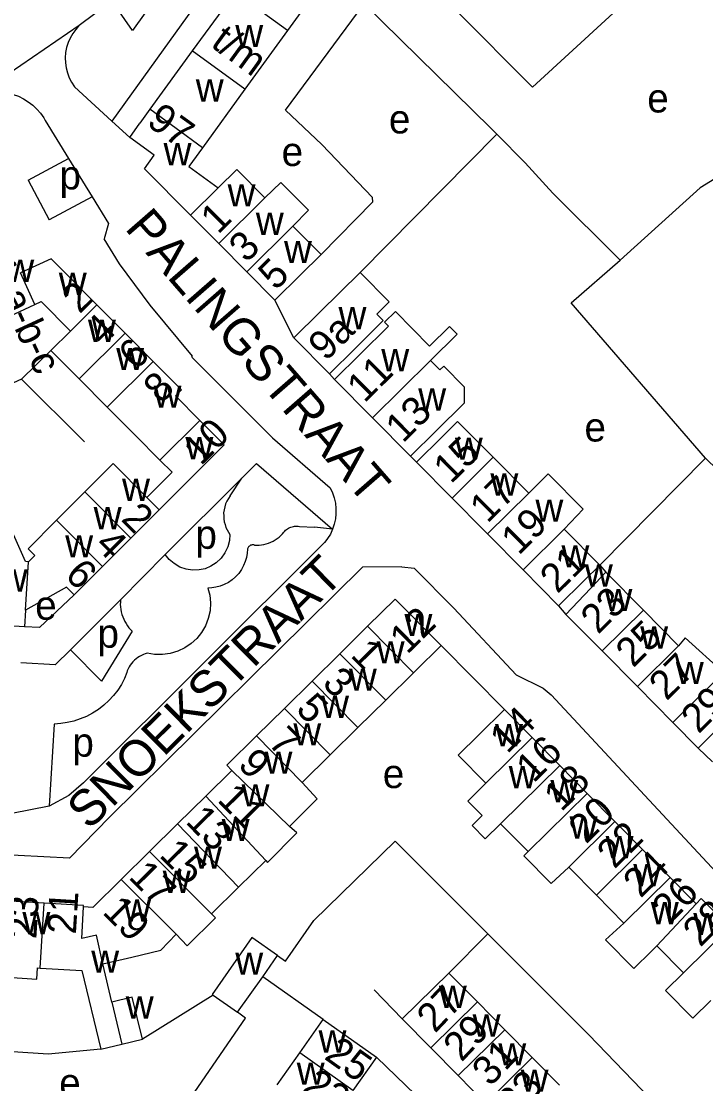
# Model space of a CAD drawing. Extents: x 159700 to 161346, y 381730 to 382922.
# Drawn here: x 160594.1 to 160688.9, y 382582.1 to 382729.2 of the extents above; entities that cross this region are included whole.
import ezdxf

# ---------------------------------------------------------------- set-up
doc = ezdxf.new("R2010")
doc.units = 0
for name, color, linetype in [('BLT_Basislijn', 7, 'Continuous'), ('BLT_Bebouwing', 7, 'Continuous'), ('BLT_Centroide', 7, 'Continuous'), ('BLT_Huisnummer', 7, 'Continuous'), ('BLT_Huisnummer_ tussenligend', 7, 'Continuous'), ('BLT_Huisnummer_reeks', 7, 'Continuous'), ('BLT_Onderdoorgang_en_onderverdeling', 7, 'Continuous'), ('BLT_Onderverdeling_panden', 7, 'Continuous'), ('BLT_Straatnaam', 7, 'Continuous'), ('BLT_Vlakafsluiter', 7, 'Continuous')]:
    doc.layers.add(name, color=color, linetype=linetype)

msp = doc.modelspace()

# ---------------------------------------------------------------- linework, layer by layer
at = {"layer": 'BLT_Basislijn'}
for p, q in [((160632.8, 382751.71), (160606.71, 382715.36)), ((160617.29, 382738.67), (160609.56, 382727.91)), ((160602.18, 382728.61), (160606.71, 382731.99)), ((160609.56, 382727.91), (160606.71, 382731.99)), ((160601.52, 382720.11), (160606.71, 382715.36)), ((160606.71, 382715.36), (160609.19, 382713.09)), ((160660.02, 382713.52), (160641.07, 382694.4)), ((160595.09, 382707.16), (160600.71, 382710.17)), ((160595.09, 382707.16), (160598.02, 382701.68)), ((160603.97, 382704.87), (160598.02, 382701.68)), ((160631.91, 382685.36), (160629.29, 382690.56)), ((160598.26, 382683.58), (160594.18, 382679.64)), ((160637.54, 382679.56), (160636.84, 382680.36)), ((160594.18, 382679.64), (160572.14, 382669.39)), ((160594.18, 382679.64), (160602.92, 382670.96)), ((160628.93, 382671.5), (160636.95, 382664.56)), ((160648.88, 382668.14), (160648.05, 382668.95)), ((160674.27, 382653.9), (160688.9, 382668.67)), ((160700, 382657.9), (160688.9, 382668.67)), ((160624.71, 382665.92), (160626.75, 382667.95)), ((160626.75, 382667.95), (160637.27, 382658.85)), ((160614.1, 382655.34), (160624.71, 382665.92)), ((160623.06, 382663.46), (160624.71, 382665.92)), ((160632.68, 382659.24), (160634.78, 382659.12)), ((160637.27, 382658.85), (160634.78, 382659.12)), ((160636.16, 382657), (160602.77, 382623.76)), ((160636.49, 382657.43), (160636.16, 382657)), ((160614.1, 382655.34), (160607.9, 382649.1)), ((160607.9, 382649.1), (160600.95, 382642.16)), ((160609.51, 382644.72), (160605.25, 382637.83)), ((160598.86, 382640.07), (160600.95, 382642.16)), ((160600.95, 382642.16), (160605.25, 382637.83)), ((160652.31, 382642.74), (160661.07, 382633.9)), ((160598.86, 382640.07), (160594.11, 382640.37)), ((160598.72, 382631.89), (160598.03, 382620.53)), ((160689.9, 382626.67), (160687.91, 382628.56)), ((160602.77, 382623.76), (160600.72, 382622.01)), ((160600.72, 382622.01), (160598.03, 382620.53)), ((160598.03, 382620.53), (160592.85, 382619.51)), ((160653.35, 382597.42), (160658.77, 382602.84)), ((160658.77, 382602.84), (160672.75, 382588.87)), ((160635.96, 382590.98), (160627.6, 382596.91)), ((160646.92, 382591.08), (160643.02, 382595.08)), ((160625.22, 382591.19), (160624.12, 382591.99)), ((160615.96, 382577.74), (160625.22, 382591.19)), ((160682.67, 382578.61), (160672.75, 382588.87)), ((160643.35, 382585.79), (160650.07, 382579.26))]:
    msp.add_line(p, q, dxfattribs=at)
for points in [[(160635.68, 382696.9), (160642.83, 382704.15), (160642.78, 382704.76), (160635.77, 382712.11), (160630.74, 382716.84), (160641.65, 382731.58)], [(160660.02, 382713.52), (160659.18, 382714.37), (160641.65, 382731.58)], [(160602.18, 382728.61), (160601.73, 382728.04), (160601.3, 382727.47), (160600.94, 382726.85), (160600.65, 382726.21), (160600.43, 382725.53), (160600.3, 382724.83), (160600.24, 382724.12), (160600.26, 382723.41), (160600.36, 382722.7), (160600.54, 382722.01), (160600.79, 382721.35), (160601.12, 382720.72), (160601.52, 382720.11)], [(160587.66, 382718.71), (160588.39, 382718.99), (160589.14, 382719.2), (160589.92, 382719.33), (160590.7, 382719.38), (160591.48, 382719.35), (160592.25, 382719.24), (160593.01, 382719.05), (160593.75, 382718.78), (160594.45, 382718.44), (160595.12, 382718.03), (160595.74, 382717.55), (160596.31, 382717.02), (160596.82, 382716.43), (160597.27, 382715.79), (160597.47, 382715.45)], [(160597.47, 382715.45), (160600.71, 382710.17)], [(160677.09, 382696.09), (160667.76, 382705.35), (160663.92, 382709.58), (160660.02, 382713.52)], [(160600.71, 382710.17), (160603.97, 382704.87)], [(160692.82, 382708.99), (160688.16, 382706.12), (160677.09, 382696.09)], [(160603.97, 382704.87), (160606.24, 382701.18), (160605.63, 382699.03)], [(160628.93, 382671.5), (160617.78, 382682.66), (160617.87, 382682.82), (160612.01, 382689.89), (160607.76, 382695.61), (160605.63, 382699.03)], [(160688.9, 382668.67), (160670.3, 382690.2), (160677.09, 382696.09)], [(160636.95, 382664.56), (160637.26, 382663.89), (160637.5, 382663.19), (160637.66, 382662.47), (160637.74, 382661.74), (160637.74, 382661), (160637.66, 382660.27), (160637.5, 382659.55), (160637.27, 382658.85)], [(160623.06, 382663.46), (160622.85, 382663.1), (160622.64, 382662.73), (160622.45, 382662.36), (160622.35, 382661.94), (160622.24, 382661.53), (160622.18, 382661.11), (160622.19, 382660.69), (160622.2, 382660.27), (160622.27, 382659.87), (160622.38, 382659.49), (160622.49, 382659.1), (160622.66, 382658.77), (160622.85, 382658.45), (160623.03, 382658.14)], [(160623.03, 382658.14), (160622.97, 382657.28), (160622.75, 382656.42), (160622.36, 382655.58), (160621.82, 382654.83), (160621.15, 382654.2), (160620.4, 382653.72), (160619.61, 382653.39), (160618.77, 382653.21), (160617.88, 382653.18), (160616.97, 382653.32), (160616.1, 382653.62), (160615.31, 382654.09), (160614.63, 382654.67), (160614.1, 382655.34)], [(160626.46, 382656.65), (160626.78, 382656.64), (160627.11, 382656.66), (160627.43, 382656.69), (160627.76, 382656.75), (160628.09, 382656.83), (160628.41, 382656.93), (160628.72, 382657.06), (160629.02, 382657.21), (160629.31, 382657.38), (160629.59, 382657.56), (160629.85, 382657.77), (160630.1, 382657.99), (160630.32, 382658.22), (160630.53, 382658.46)], [(160630.53, 382658.46), (160630.64, 382658.59), (160630.76, 382658.71), (160630.89, 382658.82), (160631.03, 382658.92), (160631.18, 382659.01), (160631.34, 382659.08), (160631.5, 382659.15), (160631.67, 382659.2), (160631.84, 382659.24), (160632.01, 382659.27), (160632.18, 382659.28), (160632.35, 382659.28), (160632.52, 382659.27), (160632.68, 382659.24)], [(160637.27, 382658.85), (160636.96, 382658.18), (160636.58, 382657.55), (160636.49, 382657.43)], [(160626.46, 382656.65), (160626.38, 382656.67), (160626.29, 382656.69), (160626.2, 382656.69), (160626.11, 382656.68), (160626.02, 382656.66), (160625.92, 382656.63), (160625.84, 382656.59), (160625.75, 382656.53), (160625.68, 382656.47), (160625.62, 382656.4), (160625.56, 382656.32), (160625.52, 382656.24), (160625.49, 382656.16), (160625.47, 382656.08)], [(160625.47, 382656.08), (160625.43, 382655.52), (160625.33, 382654.95), (160625.17, 382654.37), (160624.94, 382653.81), (160624.64, 382653.26), (160624.27, 382652.74), (160623.84, 382652.26), (160623.35, 382651.84), (160622.83, 382651.48), (160622.27, 382651.19), (160621.7, 382650.97), (160621.12, 382650.82), (160620.54, 382650.74), (160619.99, 382650.71)], [(160646.87, 382653.63), (160641.41, 382653.58), (160606.37, 382618.99), (160600.81, 382613.3), (160572.37, 382614.78)], [(160646.87, 382653.63), (160648.58, 382653.45), (160654.06, 382647.94), (160662.68, 382638.7), (160666.44, 382636.83), (160667.56, 382635.94), (160691.01, 382610.72), (160700, 382601.48)], [(160619.99, 382650.71), (160620.28, 382649.72), (160620.37, 382648.65), (160620.3, 382647.56), (160620.05, 382646.49), (160619.65, 382645.48), (160619.11, 382644.55), (160618.46, 382643.74), (160617.7, 382643.03), (160616.81, 382642.43), (160615.83, 382641.96), (160614.78, 382641.64), (160613.69, 382641.5), (160612.62, 382641.51), (160611.6, 382641.68)], [(160601.49, 382649.76), (160596.68, 382645.26), (160594.62, 382645.34)], [(160607.9, 382649.1), (160607.88, 382648.77), (160607.87, 382648.43), (160607.9, 382648.09), (160607.94, 382647.74), (160608.01, 382647.4), (160608.09, 382647.06), (160608.2, 382646.73), (160608.34, 382646.41), (160608.49, 382646.09), (160608.66, 382645.79), (160608.85, 382645.5), (160609.05, 382645.22), (160609.27, 382644.96), (160609.51, 382644.72)], [(160611.6, 382641.68), (160611.33, 382641.6), (160611.06, 382641.51), (160610.79, 382641.39), (160610.53, 382641.25), (160610.28, 382641.09), (160610.05, 382640.91), (160609.82, 382640.71), (160609.61, 382640.5), (160609.42, 382640.27), (160609.25, 382640.04), (160609.09, 382639.79), (160608.96, 382639.53), (160608.84, 382639.27), (160608.75, 382639)], [(160608.75, 382639), (160608.45, 382638.17), (160608.02, 382637.37), (160607.51, 382636.59), (160606.94, 382635.85), (160606.3, 382635.15), (160605.59, 382634.5), (160604.83, 382633.92), (160604.02, 382633.4), (160603.18, 382632.95), (160602.3, 382632.59), (160601.41, 382632.3), (160600.51, 382632.09), (160599.61, 382631.95), (160598.72, 382631.89)], [(160629.66, 382599.83), (160630.74, 382599.07), (160634.67, 382604.67), (160645.95, 382615.66), (160658.77, 382602.84)], [(160620.73, 382594.33), (160610.92, 382588.25)], [(160605.18, 382586.86), (160597.86, 382586.2), (160592.98, 382586.5), (160568.15, 382587.92)]]:
    msp.add_lwpolyline(points, dxfattribs=at)
at = {"layer": 'BLT_Bebouwing'}
for p, q in [((160636.99, 382736.15), (160631.01, 382727.89)), ((160623.72, 382733.18), (160617.84, 382725.08)), ((160631.01, 382727.89), (160625.11, 382719.75)), ((160617.84, 382725.08), (160611.96, 382716.99)), ((160625.11, 382719.75), (160619.24, 382711.65)), ((160611.96, 382716.99), (160610.56, 382715.06)), ((160609.19, 382713.09), (160610.56, 382715.06)), ((160619.24, 382711.65), (160617.88, 382709.77)), ((160611.2, 382708.75), (160617.6, 382702.32)), ((160617.6, 382702.32), (160621.5, 382698.39)), ((160631.78, 382700.82), (160635.68, 382696.9)), ((160621.5, 382698.39), (160625.4, 382694.48)), ((160604.64, 382689.92), (160600.57, 382694)), ((160625.4, 382694.48), (160629.29, 382690.56)), ((160596.05, 382689.97), (160596.9, 382690.37)), ((160596.9, 382690.37), (160600.95, 382686.27)), ((160591.89, 382688.04), (160596.05, 382689.97)), ((160608.54, 382686), (160604.64, 382689.92)), ((160600.95, 382686.27), (160598.26, 382683.58)), ((160612.44, 382682.08), (160608.54, 382686)), ((160631.91, 382685.36), (160636.84, 382680.36)), ((160602.16, 382679.66), (160606.06, 382675.74)), ((160642.79, 382674.26), (160637.54, 382679.56)), ((160618.89, 382673.9), (160615.51, 382677.3)), ((160606.06, 382675.74), (160609.97, 382671.81)), ((160648.05, 382668.95), (160642.79, 382674.26)), ((160609.97, 382671.81), (160613.36, 382668.41)), ((160664.43, 382663.84), (160659.5, 382668.81)), ((160653.81, 382663.17), (160648.88, 382668.14)), ((160602.94, 382664.01), (160599.02, 382660.09)), ((160658.23, 382658.7), (160653.81, 382663.17)), ((160613.26, 382661.54), (160609.34, 382657.61)), ((160658.73, 382658.2), (160658.23, 382658.7)), ((160663.65, 382653.23), (160658.73, 382658.2)), ((160609.34, 382657.61), (160605.41, 382653.69)), ((160605.41, 382653.69), (160601.49, 382649.76)), ((160674.27, 382653.9), (160675.12, 382652.89)), ((160668.57, 382648.25), (160663.65, 382653.23)), ((160594.76, 382647.64), (160594.62, 382645.34)), ((160668.57, 382648.25), (160669.58, 382647.07)), ((160685.18, 382642.73), (160680.31, 382647.65)), ((160669.58, 382647.07), (160674.59, 382642.02)), ((160594.62, 382645.34), (160589.14, 382645.68)), ((160642.12, 382645.41), (160638.28, 382641.62)), ((160674.59, 382642.02), (160679.49, 382637.06)), ((160638.28, 382641.62), (160634.43, 382637.83)), ((160644.62, 382635.17), (160648.47, 382638.96)), ((160634.43, 382637.83), (160630.59, 382634.04)), ((160679.49, 382637.06), (160684.4, 382632.1)), ((160640.77, 382631.39), (160644.62, 382635.17)), ((160630.59, 382634.04), (160626.74, 382630.24)), ((160664.89, 382630.03), (160661.07, 382633.9)), ((160684.4, 382632.1), (160687.91, 382628.56)), ((160636.92, 382627.6), (160640.77, 382631.39)), ((160668.72, 382626.16), (160664.89, 382630.03)), ((160633.07, 382623.81), (160636.92, 382627.6)), ((160672.54, 382622.28), (160668.72, 382626.16)), ((160623.31, 382625.47), (160619.69, 382621.9)), ((160619.69, 382621.9), (160615.8, 382618.06)), ((160676.37, 382618.41), (160672.54, 382622.28)), ((160680.2, 382614.53), (160676.37, 382618.41)), ((160615.8, 382618.06), (160611.9, 382614.22)), ((160664.34, 382614.23), (160660.54, 382618.08)), ((160611.9, 382614.22), (160608.01, 382610.38)), ((160684.02, 382610.66), (160680.2, 382614.53)), ((160673.8, 382608.21), (160669.97, 382612.09)), ((160687.63, 382607.01), (160684.02, 382610.66)), ((160677.62, 382604.34), (160673.8, 382608.21)), ((160597.32, 382607.09), (160591.87, 382607.43)), ((160602.77, 382606.75), (160597.32, 382607.09)), ((160602.76, 382606.59), (160602.77, 382606.75)), ((160687.63, 382607.01), (160688.33, 382607.75)), ((160692.27, 382603.76), (160688.33, 382607.75)), ((160685.85, 382597.44), (160682.17, 382601.17)), ((160627.6, 382596.91), (160629.66, 382599.83)), ((160624.12, 382591.99), (160627.6, 382596.91)), ((160646.92, 382591.08), (160653.35, 382597.42)), ((160653.35, 382597.42), (160657.32, 382593.41)), ((160620.58, 382594.44), (160620.73, 382594.33)), ((160620.73, 382594.33), (160624.12, 382591.99)), ((160657.32, 382593.41), (160661.1, 382589.57)), ((160689.65, 382593.6), (160687.18, 382591.16)), ((160632.71, 382586.36), (160635.96, 382590.98)), ((160650.87, 382587.07), (160646.92, 382591.08)), ((160661.1, 382589.57), (160664.9, 382585.74)), ((160629.6, 382581.92), (160632.71, 382586.36)), ((160654.67, 382583.22), (160650.87, 382587.07)), ((160664.9, 382585.74), (160668.69, 382581.9)), ((160658.46, 382579.36), (160654.67, 382583.22))]:
    msp.add_line(p, q, dxfattribs=at)
for points in [[(160654.37, 382730.68), (160664.96, 382720.03), (160686.18, 382739.55)], [(160612.56, 382710.61), (160609.19, 382713.09)], [(160611.2, 382708.75), (160612.56, 382710.61)], [(160617.88, 382709.77), (160617.37, 382709.06), (160621.42, 382706.11)], [(160621.42, 382706.11), (160623.99, 382708.65), (160627.88, 382704.74)], [(160627.88, 382704.74), (160630.1, 382706.86), (160633.92, 382703.02), (160631.78, 382700.82)], [(160600.57, 382694), (160598.28, 382696.3), (160594.03, 382694.34)], [(160629.29, 382690.56), (160632.84, 382694.09), (160635.68, 382696.9)], [(160631.91, 382685.36), (160635.51, 382688.89), (160641.07, 382694.4)], [(160636.84, 382680.36), (160640.39, 382683.88), (160644.28, 382687.73), (160643.39, 382688.63), (160645.1, 382690.32), (160641.07, 382694.4)], [(160637.54, 382679.56), (160641.09, 382683.08), (160645.02, 382686.98), (160644.48, 382687.53), (160645.96, 382689), (160650.7, 382684.21), (160653.45, 382686.93), (160654.51, 382685.86), (160650.83, 382682.22)], [(160598.26, 382683.58), (160602.16, 382679.66)], [(160615.51, 382677.3), (160616.35, 382678.15), (160612.44, 382682.08)], [(160650.83, 382682.22), (160652.13, 382680.9), (160652.67, 382681.43), (160655.51, 382678.56), (160655.47, 382676.3), (160651.6, 382672.47), (160648.05, 382668.95)], [(160618.89, 382673.9), (160622.25, 382670.52), (160613.26, 382661.54)], [(160648.88, 382668.14), (160652.44, 382671.66), (160654.58, 382673.78), (160659.5, 382668.81)], [(160613.36, 382668.41), (160615.03, 382666.73), (160611.54, 382663.24)], [(160611.54, 382663.24), (160606.86, 382667.93), (160602.94, 382664.01)], [(160669.35, 382658.87), (160671.97, 382661.62), (160667.13, 382666.51), (160664.43, 382663.84)], [(160599.02, 382660.09), (160595.09, 382656.16), (160596.03, 382655.21), (160595.15, 382654.33)], [(160595.15, 382654.33), (160594.73, 382654.38), (160592.87, 382658.52), (160589.73, 382656.87), (160589.7, 382654.67)], [(160669.35, 382658.87), (160674.27, 382653.9)], [(160675.12, 382652.89), (160680.31, 382647.65)], [(160601.49, 382649.76), (160600.4, 382650.85), (160594.76, 382647.64)], [(160652.31, 382642.74), (160645.93, 382649.17), (160642.12, 382645.41)], [(160690.12, 382637.75), (160691.39, 382639), (160686.1, 382643.81), (160685.18, 382642.73)], [(160648.47, 382638.96), (160648.75, 382639.24), (160652.31, 382642.74)], [(160658.49, 382623.71), (160654.66, 382627.59), (160657.51, 382630.39), (160661.07, 382633.9)], [(160687.91, 382628.56), (160691.46, 382632.08), (160693.62, 382634.21)], [(160626.74, 382630.24), (160622.62, 382626.19), (160623.31, 382625.47)], [(160631.31, 382617.72), (160635.11, 382621.52), (160633.07, 382623.81)], [(160660.54, 382618.08), (160658.41, 382615.98), (160656.58, 382617.83), (160657.99, 382619.22), (160656.02, 382621.21), (160658.49, 382623.71)], [(160628.01, 382613), (160628.26, 382612.73), (160632.32, 382616.83), (160631.31, 382617.72)], [(160669.97, 382612.09), (160667.54, 382609.79), (160663.74, 382613.64), (160664.34, 382614.23)], [(160624.25, 382609.3), (160628.01, 382613)], [(160608.01, 382610.38), (160604.06, 382606.48), (160602.76, 382606.59)], [(160620.5, 382605.59), (160624.25, 382609.3)], [(160615.62, 382602.79), (160617.15, 382601.17), (160621.05, 382605.07), (160620.5, 382605.59)], [(160682.17, 382601.17), (160681.45, 382600.46), (160678.98, 382598.03), (160675.06, 382602.01), (160677.62, 382604.34)], [(160605.47, 382598.71), (160609.47, 382599.63), (160613.46, 382600.56), (160615.62, 382602.79)], [(160629.66, 382599.83), (160626.1, 382602.34), (160620.58, 382594.44)], [(160591.32, 382598.45), (160591.64, 382598.43), (160591.55, 382596.88), (160596.29, 382596.58), (160596.38, 382598.14), (160596.77, 382598.11)], [(160596.77, 382598.11), (160602.54, 382597.76), (160605.18, 382586.86)], [(160606.7, 382593.4), (160605.47, 382598.71)], [(160687.18, 382591.16), (160683.38, 382595), (160685.85, 382597.44)], [(160610.92, 382588.25), (160609.51, 382594.08), (160606.7, 382593.4)], [(160635.96, 382590.98), (160643.35, 382585.79), (160640.09, 382581.15)], [(160605.18, 382586.86), (160608.06, 382587.56)], [(160608.06, 382587.56), (160610.92, 382588.25)]]:
    msp.add_lwpolyline(points, dxfattribs=at)
at = {"layer": 'BLT_Onderdoorgang_en_onderverdeling'}
for points in [[(160674.27, 382653.9), (160672.12, 382651.77), (160668.57, 382648.25)], [(160669.58, 382647.07), (160673, 382650.67), (160675.12, 382652.89)]]:
    msp.add_lwpolyline(points, dxfattribs=at)
at = {"layer": 'BLT_Onderverdeling_panden'}
for p, q in [((160631.01, 382727.89), (160623.72, 382733.18)), ((160625.11, 382719.75), (160617.84, 382725.08)), ((160619.24, 382711.65), (160611.96, 382716.99)), ((160617.6, 382702.32), (160621.42, 382706.11)), ((160621.5, 382698.39), (160627.88, 382704.74)), ((160625.4, 382694.48), (160631.78, 382700.82)), ((160596.05, 382689.97), (160594.03, 382694.34)), ((160600.95, 382686.27), (160604.64, 382689.92)), ((160602.16, 382679.66), (160608.54, 382686)), ((160606.06, 382675.74), (160612.44, 382682.08)), ((160642.79, 382674.26), (160650.83, 382682.22)), ((160618.89, 382673.9), (160613.36, 382668.41)), ((160653.81, 382663.17), (160659.5, 382668.81)), ((160609.34, 382657.61), (160602.94, 382664.01)), ((160658.73, 382658.2), (160664.43, 382663.84)), ((160611.54, 382663.24), (160613.26, 382661.54)), ((160605.41, 382653.69), (160599.02, 382660.09)), ((160663.65, 382653.23), (160669.35, 382658.87)), ((160594.76, 382647.64), (160595.15, 382654.33)), ((160674.59, 382642.02), (160680.31, 382647.65)), ((160648.47, 382638.96), (160642.12, 382645.41)), ((160679.49, 382637.06), (160685.18, 382642.73)), ((160644.62, 382635.17), (160638.28, 382641.62)), ((160640.77, 382631.39), (160634.43, 382637.83)), ((160684.4, 382632.1), (160690.12, 382637.75)), ((160636.92, 382627.6), (160630.59, 382634.04)), ((160633.07, 382623.81), (160626.74, 382630.24)), ((160658.49, 382623.71), (160664.89, 382630.03)), ((160660.54, 382618.08), (160668.72, 382626.16)), ((160631.31, 382617.72), (160623.31, 382625.47)), ((160628.01, 382613), (160619.69, 382621.9)), ((160664.34, 382614.23), (160672.54, 382622.28)), ((160669.97, 382612.09), (160676.37, 382618.41)), ((160624.25, 382609.3), (160615.8, 382618.06)), ((160620.5, 382605.59), (160611.9, 382614.22)), ((160673.8, 382608.21), (160680.2, 382614.53)), ((160615.62, 382602.79), (160608.01, 382610.38)), ((160677.62, 382604.34), (160684.02, 382610.66)), ((160596.77, 382598.11), (160597.32, 382607.09)), ((160682.17, 382601.17), (160687.63, 382607.01)), ((160685.85, 382597.44), (160692.27, 382603.76)), ((160606.7, 382593.4), (160608.06, 382587.56)), ((160650.87, 382587.07), (160657.32, 382593.41)), ((160661.1, 382589.57), (160654.67, 382583.22)), ((160640.09, 382581.15), (160632.71, 382586.36)), ((160658.46, 382579.36), (160664.9, 382585.74))]:
    msp.add_line(p, q, dxfattribs=at)
msp.add_lwpolyline([(160605.47, 382598.71), (160604.55, 382602.68), (160602.55, 382602.22), (160602.76, 382606.59)], dxfattribs=at)
at = {"layer": 'BLT_Vlakafsluiter'}
msp.add_line((160587.66, 382718.71), (160602.18, 382728.61), dxfattribs=at)

# ---------------------------------------------------------------- texts
at = {"layer": 'BLT_Centroide'}
for s, p in [('w', (160623.79, 382725.59)), ('w', (160618.32, 382718.06)), ('e', (160680.85, 382716.54)), ('e', (160645.07, 382713.64)), ('w', (160613.86, 382709.23)), ('e', (160630.21, 382709.13)), ('p', (160599.45, 382705.89)), ('w', (160622.73, 382703.53)), ('w', (160626.64, 382699.59)), ('w', (160630.54, 382695.69)), ('w', (160592.08, 382693.09)), ('w', (160599.35, 382691.28)), ('w', (160638.09, 382686.53)), ('w', (160603.39, 382684.78)), ('w', (160607.3, 382680.88)), ('w', (160644.01, 382680.72)), ('w', (160612.47, 382675.66)), ('w', (160649.13, 382675.28)), ('e', (160672.15, 382670.99)), ('w', (160616.89, 382668.53)), ('w', (160654.2, 382668.47)), ('w', (160608.11, 382662.77)), ('w', (160659.12, 382663.5)), ('w', (160665.36, 382659.88)), ('w', (160604.18, 382658.84)), ('w', (160600.24, 382654.94)), ('p', (160618.27, 382656.14)), ('w', (160668.96, 382653.56)), ('w', (160672.21, 382650.91)), ('w', (160591.17, 382650.23)), ('w', (160674.92, 382647.52)), ('e', (160596.08, 382646.32)), ('w', (160647.22, 382644.05)), ('p', (160604.71, 382642.45)), ('w', (160679.87, 382642.34)), ('w', (160643.38, 382640.28)), ('w', (160684.81, 382637.41)), ('w', (160639.53, 382636.5)), ('w', (160635.67, 382632.72)), ('w', (160631.83, 382628.92)), ('w', (160659.77, 382628.81)), ('p', (160601.23, 382627.37)), ('w', (160627.84, 382625)), ('e', (160644.22, 382623.02)), ('w', (160661.66, 382623)), ('w', (160667.43, 382621.06)), ('w', (160624.66, 382620.47)), ('w', (160621.91, 382615.69)), ('w', (160670.09, 382616.03)), ('w', (160675.08, 382613.31)), ('w', (160618.08, 382611.86)), ('w', (160678.91, 382609.44)), ('w', (160613.75, 382608.5)), ('w', (160608.26, 382604.53)), ('w', (160681.34, 382604.17)), ('w', (160594.31, 382602.78)), ('w', (160687.22, 382602.67)), ('w', (160603.84, 382597.45)), ('w', (160623.79, 382597.17)), ('w', (160651.99, 382592.59)), ('w', (160608.62, 382591.1)), ('w', (160656.66, 382588.61)), ('w', (160635.32, 382586.41)), ('w', (160660.22, 382584.63)), ('w', (160632.3, 382581.95)), ('e', (160599.41, 382580.22)), ('w', (160663.31, 382580.99))]:
    msp.add_text(s, height=4, dxfattribs=at).set_placement(p)
at = {"layer": 'BLT_Huisnummer'}
for s, rotation, p in [('1', 44.8469, (160621.42, 382699.58)), ('5', 44.8469, (160629.4, 382691.79)), ('2', 44.8648, (160602.22, 382688.57)), ('9a', 44.7083, (160636.33, 382681.99)), ('6', 44.7038, (160610.05, 382680.74)), ('11', 44.7069, (160641.68, 382676.23)), ('10', 44.6738, (160619.01, 382667.53)), ('15', 44.7083, (160653.66, 382665.02)), ('2', 314.9955, (160607.84, 382660.13)), ('19', 44.7171, (160663.04, 382655.15)), ('6', 314.9062, (160600.04, 382652.34)), ('23', 44.7083, (160674.05, 382644.21)), ('12', 44.53, (160647.59, 382641.42)), ('1', 314.5294, (160639.63, 382641.3)), ('5', 314.5287, (160632.03, 382633.78)), ('29', 44.7124, (160687.95, 382630.43)), ('14', 44.6397, (160661.46, 382627.65)), ('9', 314.6041, (160624, 382626.11)), ('18', 44.6396, (160668.94, 382619.62)), ('13', 314.6086, (160616.76, 382618.27)), ('22', 44.6395, (160676.3, 382611.72)), ('17', 314.6041, (160608.88, 382610.61)), ('26', 44.6398, (160683.95, 382604.12)), ('21', 86.4674, (160601.71, 382602.71)), ('27', 46.6261, (160651.45, 382588.98)), ('25', 324.6261, (160635.96, 382585.62)), ('31', 46.6261, (160659.12, 382581.58))]:
    msp.add_text(s, height=4, rotation=rotation, dxfattribs=at).set_placement(p)
at = {"layer": 'BLT_Huisnummer_ tussenligend'}
for s, rotation, p in [('3', 44.8469, (160625.34, 382695.62)), ('4', 44.8648, (160605.44, 382684.11)), ('8', 44.7038, (160613.49, 382676.1)), ('13', 44.7069, (160647.01, 382670.66)), ('17', 44.7083, (160658.7, 382659.56)), ('4', 314.9955, (160604.2, 382656.51)), ('21', 44.7171, (160668.41, 382649.82)), ('25', 44.7083, (160678.89, 382639.57)), ('27', 44.7124, (160683.51, 382635)), ('3', 314.5294, (160635.68, 382637.38)), ('7', 314.5287, (160628.18, 382629.14)), ('16', 44.6397, (160665.09, 382623.61)), ('11', 314.6041, (160621.17, 382621.28)), ('20', 44.6396, (160672.37, 382615.17)), ('15', 314.6086, (160613.13, 382613.62)), ('24', 44.6395, (160679.92, 382607.67)), ('23', 86.4674, (160596.23, 382602.06)), ('19', 314.6041, (160605.25, 382605.75)), ('28', 44.6398, (160688.19, 382600.9)), ('29', 46.6261, (160655.13, 382584.99)), ('23', 324.6261, (160632.95, 382581.2)), ('33', 46.6261, (160662.59, 382577.28))]:
    msp.add_text(s, height=4, rotation=rotation, dxfattribs=at).set_placement(p)
at = {"layer": 'BLT_Huisnummer_reeks'}
for s, rotation, p in [('t/m', 324.0207, (160620.23, 382725.76)), ('97', 324.2847, (160611.35, 382714.88)), ('1-a-b-c', 294.8177, (160589.15, 382695.39))]:
    msp.add_text(s, height=4, rotation=rotation, dxfattribs=at).set_placement(p)
at = {"layer": 'BLT_Straatnaam'}
for s, rotation, p in [('PALINGSTRAAT', 311.0587, (160608.37, 382700.46)), ('SNOEKSTRAAT', 44.6264, (160603.54, 382617.08))]:
    msp.add_text(s, height=5, rotation=rotation, dxfattribs=at).set_placement(p)

doc.saveas('drawing.dxf')
